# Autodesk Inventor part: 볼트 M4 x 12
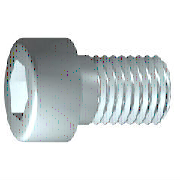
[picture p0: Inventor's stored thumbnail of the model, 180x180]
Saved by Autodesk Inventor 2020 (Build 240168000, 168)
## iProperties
Created: 2012-02
Part Number: 볼트 M4 x 12
Material: 강철, 연강
Description: 원통형 머리 캡 나사
Document SubType Name: Modeling
Standard: JIS B 1176
Designer: mdu-01
Standards Organization: JIS
Language: ko-KR
Size Designation: M4 x 12
Categories: <MemberInstance><Categories><Category DisplayName="조임쇠" InternalName="e4da775c-781d-43d5-af7c-5136215cf5a6" Mnemonic="FSTN"><Category DisplayName="볼트" InternalN
Density: 1 g/cm^3
Appearance: 강철
IsCustomPart: 1
Author: mdu-01
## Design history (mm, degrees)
sketch "스케치1"
  geometry: L1 (-1, 0)-(12, 0); L2 (12, 0)-(12, 2); L3 (12, 2)-(1.75, 2); L4 (1.75, 2)-(1.32, 2); L5 (1.32, 2)-(0, 2); L6 (0, 2)-(0, 3.5); L7 (0, 3.5)-(-4, 3.5); L8 (-4, 3.5)-(-4, 1.732); L9 (-4, 1.732)-(-2, 1.732); L10 (-2, 1.732)-(-1, 0); L11 (-7.2, 0)-(15.2, 0) reference; L12 (0, -0.7)-(0, 4.2) reference; L13 (1.75, 2)-(0, 2)
  constraints: 22 end point, 6 parallel, 2 collinear, 2 perpendicular, 1 horizontal, 1 point on line
  dimensions: "d1" = 10.25 distance from line of L3.end L2 (= GEL); "d2" = 0.42952 distance of L4.end L3.end (computed from GAL); "d3" = 4 distance between parallel lines of L8 L6 (= KOH); "d4" = 2 distance of L8.end L9.end (= INTI); "d5" = 60 deg angle of L10 L1; "d6" = 4 diameter of L3 L1 (= GD); "d7" = 4 diameter of L5 L1 (= BDM); "d8" = 3.4641 diameter of L9 L1 (= 1.1547 x SW); "d9" = 7 diameter of L7 L1 (= KOD); "d26" = 12 distance between parallel lines of L12 L2 (= NLG)
revolve "본체" sketch "스케치1" stored, may be unused: angle "d10" = 90 deg
sketch "스케치2"
  geometry: L1 (0, -4.9)-(0, 4.9) reference; L2 (-4.9, 0)-(4.9, 0) reference; L3 (1.732, 0)-(0.866, -1.5); L4 (0.866, -1.5)-(-0.866, -1.5); L5 (-0.866, -1.5)-(-1.732, 0); L6 (-1.732, 0)-(-0.866, 1.5); L7 (-0.866, 1.5)-(0.866, 1.5); L8 (0.866, 1.5)-(1.732, 0); 2 further points
  constraints: 12 end point, 1 coincident, 1 horizontal alignment, 1 point on line, 12 other
extrude "슬롯" join sketch "스케치2" stored distance "d11" = 10; taper "d12" = 0 deg
workplane "Work Plane1"
fillet "Fillet2" dims "d30" = 0.1 (= R)
body "Solid1"
fillet "모깎기1" dims "d17" = 0.4 (= RR)
feature "스레드" dims "d13" = 10.25 (= GEL), "d14" = 0
chamfer "모따기1" distance "d15" = 0.42941 (= -0.5 x SPD + 0.5 x GD); stored, may be unused: second distance "d16" = 0.42941 (= GUL), angle "d27" = 45 deg
other parameters: "GD" = 4 (= NND) [user parameter; used in 2 equation terms], "NLG" = 12 [user parameter; used in 1 equation term], "GEL" = 10.25 [user parameter; used in 2 equation terms], "KOD" = 7 [user parameter; used in 1 equation term], "KOH" = 4 [user parameter; used in 1 equation term], "INTI" = 2 [user parameter; used in 1 equation term], "GAL" = 0.42941 (= 0.61345 x PTC) [user parameter; used in 1 equation term], "GUL" = 0.42941 (= 0.61345 x PTC) [user parameter; used in 1 equation term], "BDM" = 4 (= NND) [user parameter; used in 1 equation term], "SW" = 3 [user parameter; used in 2 equation terms], "RR" = 0.4 [user parameter; used in 1 equation term], "SPD" = 3.14117 (= NND - 1.2269 x PTC) [user parameter; used in 1 equation term], "d19" = 0, "d28" = 0, "d29" = 0, "R" = 0.1 [user parameter; used in 1 equation term], "PHH" = 0.2 [user parameter], "GD1" = 3.14117 (= THREADDIA - 1.2269 x PTC) [user parameter], "THREADDIA" = 4 [user parameter; used in 1 equation term], "FAWI" = 45 deg [user parameter], "TPU" = 14.28571 (computed from PTC) [user parameter], "PTC" = 0.7 [user parameter; used in 5 equation terms], "NND" = 4 [user parameter; used in 3 equation terms], "TOA" = 30 deg [user parameter], "E0" = 3.465 (= 1.155 x SW) [user parameter]
